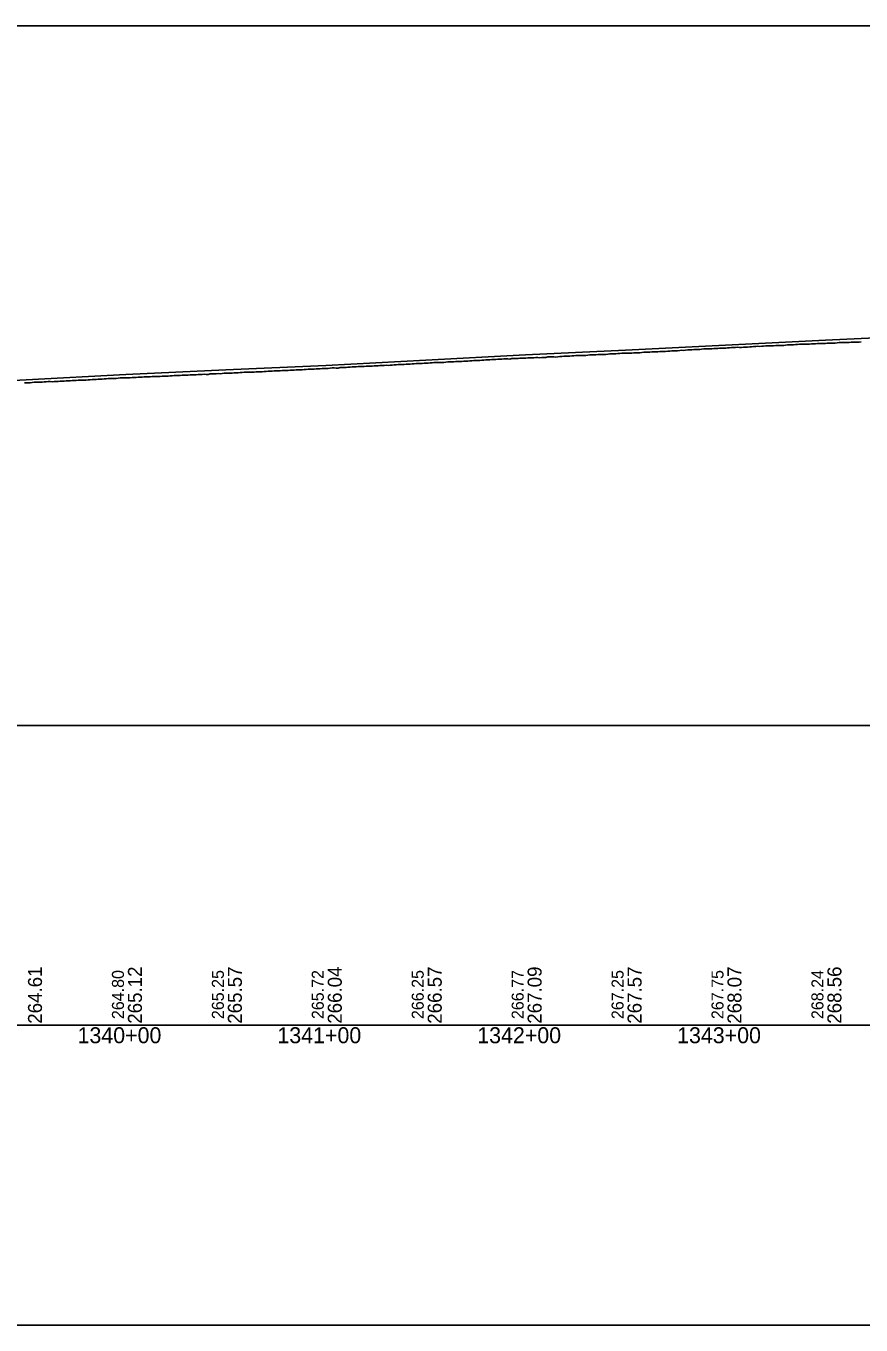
# Model space of a CAD drawing. Extents: x -3627 to 47473, y 2850 to 4350.
# Drawn here: x 21327 to 21745, y 2850 to 3500 of the extents above; entities that cross this region are included whole.
import ezdxf

# ---------------------------------------------------------------- set-up
doc = ezdxf.new("R2010")
doc.units = 0
for name, color, linetype in [('RD_DDB_Profile_EX', 7, 'Continuous'), ('RD_DDB_Profile_PR', 7, 'Continuous'), ('RD_DDB_StaTX', 7, 'Continuous'), ('RD_DDB_StripGrade', 7, 'Continuous'), ('RD_GPK_Profile_Cell', 7, 'Continuous'), ('RD_SHT_ShtClip', 7, 'Continuous')]:
    doc.layers.add(name, color=color, linetype=linetype)

msp = doc.modelspace()

# ---------------------------------------------------------------- linework, layer by layer
at = {"layer": 'RD_DDB_Profile_EX'}
for points in [[(21721.279906, 3340.96238), (21722.284866, 3341.00346), (21723.289607, 3341.055875), (21724.282754, 3341.05552), (21725.28886, 3341.128175), (21726.282012, 3341.16884), (21727.286747, 3341.199865), (21728.281277, 3341.20887), (21729.286019, 3341.225765), (21730.284526, 3341.26339), (21731.28401, 3341.305475), (21732.283915, 3341.370745), (21733.283394, 3341.51717), (21734.288157, 3341.543005), (21735.286881, 3341.605035), (21736.286363, 3341.569275), (21737.284874, 3341.647355), (21738.284407, 3341.648115), (21739.284391, 3341.675975), (21740.289168, 3341.74278), (21741.282485, 3341.829255), (21742.288699, 3341.859025), (21743.282029, 3341.817335), (21744.286788, 3341.865575), (21745.293011, 3341.935395)], [(21521.484962, 3330.98291), (21522.486469, 3331.036555), (21523.483475, 3331.056375), (21524.484984, 3331.191505), (21525.487879, 3331.185385), (21526.484135, 3331.209645), (21527.485674, 3331.26289), (21528.482043, 3331.363835), (21529.477783, 3331.419265), (21530.480108, 3331.46374), (21531.475992, 3331.55614), (21532.472546, 3331.57364), (21533.48216, 3331.536715), (21534.478043, 3331.624935), (21535.479844, 3331.62775), (21536.475731, 3331.636655), (21537.47285, 3331.82518), (21538.474875, 3331.885625), (21539.470977, 3331.88607), (21540.467583, 3331.93277), (21541.469623, 3331.989075), (21542.473688, 3332.04077), (21543.46979, 3332.08731), (21544.472334, 3332.136075), (21545.468509, 3332.19021), (21546.470685, 3332.288925), (21547.467485, 3332.29289), (21548.463696, 3332.34335), (21549.466466, 3332.441955), (21550.470053, 3332.489895), (21551.466269, 3332.59036), (21552.469055, 3332.685465), (21553.464884, 3332.642815), (21554.461888, 3332.685585), (21555.46434, 3332.74133), (21556.461335, 3332.841245), (21557.463799, 3332.87965), (21558.460786, 3332.882995), (21559.4646, 3333.026765), (21560.467623, 3333.072055), (21561.464136, 3333.07204), (21562.466398, 3333.18761), (21563.463593, 3333.237145), (21564.466313, 3333.239035), (21565.463503, 3333.291945), (21566.392591, 3333.384595), (21567.456032, 3333.4297), (21568.38762, 3333.42905), (21569.456011, 3333.366475), (21570.45247, 3333.54319), (21571.455437, 3333.59149), (21572.452818, 3333.64706), (21573.455789, 3333.59216), (21574.453167, 3333.77531), (21575.456143, 3333.842825), (21576.453517, 3333.83879), (21577.456566, 3333.84964), (21578.454152, 3333.873095), (21579.456938, 3333.874265), (21580.454518, 3333.891895), (21581.457719, 3333.989885), (21582.454799, 3334.038815), (21583.458583, 3334.048925), (21584.456165, 3334.000965), (21585.459517, 3334.09206), (21586.457402, 3334.046585), (21587.460892, 3334.096985), (21588.45827, 3334.37571), (21589.46227, 3334.372705), (21590.459649, 3334.44058), (21591.463561, 3334.387845), (21592.461468, 3334.3426), (21593.458926, 3334.53059), (21594.463145, 3334.67017), (21595.46075, 3334.68169), (21596.464422, 3334.77129), (21597.455687, 3334.81501), (21598.459362, 3334.768515), (21599.456978, 3334.866105), (21600.461202, 3334.93708), (21601.458891, 3334.984925), (21602.463338, 3335.038), (21603.461656, 3335.13215), (21604.465523, 3335.07812), (21605.463959, 3335.079195), (21606.467814, 3335.140215), (21607.465655, 3335.18417), (21608.47011, 3335.279755), (21609.468028, 3335.403545), (21610.472597, 3335.452925), (21611.471305, 3335.515715), (21612.475345, 3335.51088), (21613.472751, 3335.558635), (21614.476797, 3335.60784), (21615.46759, 3335.65768), (21616.472813, 3335.68137), (21617.469633, 3335.67898), (21618.473911, 3335.72388), (21619.471526, 3335.913105), (21620.475807, 3335.957865), (21621.467479, 3335.9152)], [(21621.467479, 3335.9152), (21622.471759, 3335.964045), (21623.469249, 3336.06589), (21624.473533, 3336.12293), (21625.471096, 3336.2124), (21626.475492, 3336.211265), (21627.466625, 3336.24848), (21628.471671, 3336.288695), (21629.468734, 3336.31522), (21630.390928, 3336.268105), (21631.470843, 3336.46965), (21632.475233, 3336.47269), (21633.466448, 3336.459745), (21634.471726, 3336.52467), (21635.392044, 3336.66055), (21636.473634, 3336.711975), (21637.478904, 3336.72295), (21638.476207, 3336.76156), (21639.388938, 3336.8492), (21640.472861, 3336.90898), (21641.39126, 3336.95298), (21642.475065, 3336.962605), (21643.480001, 3336.97345), (21644.47754, 3337.06993), (21645.387454, 3337.066225), (21646.474662, 3337.17577), (21647.38977, 3337.17414), (21648.476987, 3337.26607), (21649.48256, 3337.3095), (21650.474436, 3337.371745), (21651.386658, 3337.415185), (21652.477936, 3337.420095), (21653.388975, 3337.463475), (21654.480689, 3337.563995), (21655.48641, 3337.742755), (21656.478314, 3337.69599), (21657.385875, 3337.78396), (21658.482128, 3337.883835), (21659.388195, 3337.926215), (21660.485304, 3338.0012), (21661.491255, 3338.043555), (21662.483425, 3338.08153), (21663.488562, 3338.123805), (21664.494511, 3338.199795), (21665.387439, 3338.289315), (21666.490829, 3338.38902), (21667.497011, 3338.37973), (21668.495243, 3338.42946), (21669.391424, 3338.425885), (21670.499658, 3338.508075), (21671.49789, 3338.61333), (21672.503185, 3338.65477), (21673.496629, 3338.696185), (21674.387155, 3338.736945), (21675.385258, 3338.74783), (21676.499071, 3338.70872), (21677.386874, 3338.74965), (21678.385909, 3338.93161), (21679.383288, 3338.98134), (21680.387727, 3339.04003), (21681.385831, 3339.0393), (21682.388565, 3339.13589), (21683.387636, 3339.22289), (21684.38574, 3339.152645), (21685.390188, 3339.18068), (21686.387523, 3339.317485), (21687.512546, 3339.32291), (21688.390069, 3339.319195), (21689.51672, 3339.487875), (21690.384954, 3339.52563), (21691.384112, 3339.54447), (21692.38141, 3339.5436), (21693.385885, 3339.75646), (21694.383997, 3339.705035), (21695.518659, 3339.724665), (21696.385743, 3339.80717), (21697.524253, 3339.89879), (21698.388339, 3339.894525), (21699.385581, 3339.93603), (21700.528196, 3340.034265), (21701.388174, 3340.02992), (21702.532956, 3340.10797), (21703.389867, 3340.14668), (21704.389159, 3340.187835), (21705.537845, 3340.18648), (21706.543821, 3340.20479), (21707.382285, 3340.28584), (21708.381646, 3340.376325), (21709.383971, 3340.45629), (21710.542998, 3340.460085), (21711.386621, 3340.45643), (21712.385034, 3340.622755), (21713.38316, 3340.66242), (21714.387714, 3340.716205), (21715.384819, 3340.747505), (21716.382944, 3340.79499), (21717.387497, 3340.81615), (21718.385625, 3340.80518), (21719.389113, 3340.8689), (21720.398576, 3340.89002), (21721.279906, 3340.96238)], [(21421.490592, 3325.923885), (21422.485733, 3325.924385), (21423.493954, 3326.06549), (21424.489092, 3326.016025), (21425.491602, 3326.08201), (21426.486236, 3326.21881), (21427.494669, 3326.27306), (21428.490029, 3326.305105), (21429.492684, 3326.32096), (21430.49534, 3326.323395), (21431.489973, 3326.369105), (21432.498387, 3326.459455), (21433.493847, 3326.518855), (21434.496723, 3326.56147), (21435.492341, 3326.656485), (21436.500192, 3326.70128), (21437.494884, 3326.75186), (21438.497586, 3326.76892), (21439.498803, 3326.82107), (21440.49426, 3326.81656), (21441.494946, 3326.82786), (21442.4971, 3326.906685), (21443.492773, 3326.947045), (21444.494212, 3326.99919), (21445.489878, 3327.01325), (21446.49781, 3327.10825), (21447.492872, 3327.10795), (21448.494324, 3327.25061), (21449.490058, 3327.30039), (21450.49242, 3327.30226), (21451.49409, 3327.399225), (21452.48997, 3327.439305), (21453.491633, 3327.395815), (21454.49414, 3327.44232), (21455.495059, 3327.539675), (21456.490937, 3327.6081), (21457.492684, 3327.650225), (21458.495997, 3327.646705), (21459.491332, 3327.800955), (21460.492611, 3327.852025), (21461.488707, 3327.81081), (21462.497797, 3327.954765), (21463.493127, 3328.00425), (21464.495025, 3328.000675), (21465.491199, 3327.999745), (21466.494708, 3328.055965), (21467.496181, 3328.111545), (21468.491717, 3328.25081), (21469.49383, 3328.296745), (21470.497312, 3328.282935), (21471.499426, 3328.3339), (21472.495763, 3328.47761), (21473.496498, 3328.47852), (21474.500166, 3328.52411), (21475.496724, 3328.572475), (21476.498381, 3328.57802), (21477.494945, 3328.586955), (21478.497272, 3328.55846), (21479.499599, 3328.838035), (21480.501255, 3328.877905), (21481.496539, 3328.910545), (21482.498267, 3328.77131), (21483.500808, 3328.831715), (21484.495564, 3329.07933), (21485.492316, 3329.082365), (21486.494856, 3329.092705), (21487.490241, 3329.11536), (21488.492139, 3329.305345), (21489.494754, 3329.355395), (21490.497508, 3329.40023), (21491.493092, 3329.48777), (21492.494431, 3329.497475), (21493.497185, 3329.54729), (21494.492767, 3329.64481), (21495.489725, 3329.642495), (21496.491846, 3329.69701), (21497.487494, 3329.744395), (21498.490467, 3329.79383), (21499.493441, 3329.843265), (21500.495782, 3329.842465), (21501.490793, 3329.944835), (21502.493764, 3329.90887), (21503.496736, 3329.96324), (21504.491894, 3330.150385), (21505.489147, 3330.15255), (21506.49234, 3330.19672), (21507.487557, 3330.20354), (21508.489969, 3330.193115), (21509.493007, 3330.242695), (21510.496195, 3330.301645), (21511.491424, 3330.448625), (21512.494462, 3330.43842), (21513.496944, 3330.57285), (21514.493174, 3330.593855), (21515.489991, 3330.640725), (21516.493243, 3330.599945), (21517.488693, 3330.776685), (21518.491303, 3330.78554), (21519.493987, 3330.79903), (21520.489437, 3330.89094), (21521.484962, 3330.98291)], [(21326.496332, 3321.382035), (21327.496333, 3321.4346), (21328.496472, 3321.44598), (21329.495944, 3321.45266), (21330.496861, 3321.5862), (21331.490633, 3321.694905), (21332.491535, 3321.69676), (21333.491143, 3321.70311), (21334.492025, 3321.71371), (21335.491645, 3321.802435), (21336.492508, 3321.904315), (21337.486348, 3321.995185), (21338.486718, 3322.051285), (21339.487217, 3322.0526), (21340.487052, 3322.012515), (21341.48808, 3322.059855), (21342.487926, 3322.1114), (21343.488938, 3322.17098), (21344.48291, 3322.21212), (21345.483977, 3322.31752), (21346.484026, 3322.31865), (21347.484588, 3322.36604), (21348.485271, 3322.420885), (21349.485336, 3322.4759), (21350.480624, 3322.566905), (21351.480683, 3322.6336), (21352.481854, 3322.68461), (21353.481986, 3322.727905), (21354.483347, 3322.72861), (21355.48362, 3322.73312), (21356.47848, 3322.774205), (21357.479355, 3322.828535), (21358.480108, 3322.975695), (21359.48098, 3322.979985), (21360.481257, 3323.08073), (21361.48267, 3323.13503), (21362.477257, 3323.183175), (21363.478812, 3323.279735), (21364.479288, 3323.283845), (21365.480242, 3323.29184), (21366.475313, 3323.36757), (21367.476266, 3323.460635), (21368.483987, 3323.53134), (21369.485013, 3323.535565), (21370.486174, 3323.63191), (21371.481448, 3323.679875), (21372.482609, 3323.680035), (21373.483277, 3323.82614), (21374.484438, 3323.87244), (21375.4856, 3323.87647), (21376.480881, 3323.9283), (21377.482109, 3324.020485), (21378.483476, 3323.978125), (21379.484843, 3323.96216), (21380.48621, 3324.05403), (21381.480562, 3324.125345), (21382.481928, 3324.109025), (21383.483294, 3324.22089), (21384.48466, 3324.27067), (21385.486095, 3324.274375), (21386.481808, 3324.371625), (21387.483382, 3324.471045), (21388.484955, 3324.516285), (21389.493823, 3324.512995), (21390.489005, 3324.555585), (21391.490575, 3324.600575), (21392.492146, 3324.61759), (21393.493787, 3324.56691), (21394.494854, 3324.661775), (21395.490807, 3324.749575), (21396.492583, 3324.79398), (21397.494358, 3324.79756), (21398.488316, 3324.858215), (21399.490093, 3324.89806), (21400.490437, 3324.95657), (21401.492285, 3325.059975), (21402.494271, 3325.06777), (21403.489007, 3325.118965), (21404.496089, 3325.165495), (21405.490818, 3325.257855), (21406.492805, 3325.26097), (21407.487528, 3325.321145), (21408.489522, 3325.315415), (21409.489417, 3325.36451), (21410.491615, 3325.41723), (21411.486537, 3325.42252), (21412.488743, 3325.47092), (21413.489472, 3325.57382), (21414.49168, 3325.61781), (21415.493176, 3325.661945), (21416.488102, 3325.771715), (21417.490382, 3325.674475), (21418.491322, 3325.67694), (21419.493745, 3325.86166), (21420.488169, 3325.9036), (21421.490592, 3325.923885)]]:
    msp.add_lwpolyline(points, dxfattribs=at)
at = {"layer": 'RD_DDB_Profile_PR'}
msp.add_lwpolyline([(21277.33, 3320.287), (21327.33, 3323.026), (21377.33, 3325.6065), (21427.33, 3327.864), (21477.33, 3330.1855), (21527.33, 3332.8545), (21577.33, 3335.4485), (21627.33, 3337.8435), (21677.33, 3340.347), (21727.33, 3342.8005), (21777.33, 3345.182), (21827.33, 3347.6195), (21877.33, 3350.0485), (21927.33, 3352.6315), (21977.33, 3355.0435), (22027.33, 3357.7015), (22077.33, 3359.962), (22127.33, 3362.5345), (22177.33, 3365.2075), (22227.33, 3367.6435)], dxfattribs=at)
at = {"layer": 'RD_GPK_Profile_Cell'}
msp.add_line((1000, 3000), (46705.077602, 3000), dxfattribs=at)
at = {"layer": 'RD_SHT_ShtClip'}
for points in [[(20453.33, 3500), (20453.33, 3000), (21953.33, 3000), (21953.33, 3000), (21953.33, 3500), (21953.33, 3500)], [(20433.33, 3150), (21973.33, 3150), (21973.33, 2850), (20433.33, 2850)]]:
    msp.add_lwpolyline(points, close=True, dxfattribs=at)

# ---------------------------------------------------------------- texts
at = {"layer": 'RD_DDB_StaTX'}
for s, p in [('1340+00', (21353.125471, 2991)), ('1341+00', (21453.125471, 2991)), ('1342+00', (21553.125471, 2991)), ('1343+00', (21653.125471, 2991))]:
    msp.add_text(s, height=8, dxfattribs=at).set_placement(p)
at = {"layer": 'RD_DDB_StripGrade'}
for s, height, p in [('266.04', 7, (21485.33, 3000.75)), ('264.61', 7, (21335.33, 3000.75)), ('264.80', 6, (21376.33, 3003.073688)), ('265.12', 7, (21385.33, 3000.75)), ('265.25', 6, (21426.33, 3003.073688)), ('265.57', 7, (21435.33, 3000.75)), ('265.72', 6, (21476.33, 3003.073688)), ('266.25', 6, (21526.33, 3003.073688)), ('266.57', 7, (21535.33, 3000.75)), ('266.77', 6, (21576.33, 3003.073688)), ('267.09', 7, (21585.33, 3000.75)), ('267.25', 6, (21626.33, 3003.073688)), ('267.57', 7, (21635.33, 3000.75)), ('267.75', 6, (21676.33, 3003.073688)), ('268.07', 7, (21685.33, 3000.75)), ('268.24', 6, (21726.33, 3003.073688)), ('268.56', 7, (21735.33, 3000.75))]:
    msp.add_text(s, height=height, rotation=90, dxfattribs=at).set_placement(p)

doc.saveas('drawing.dxf')
